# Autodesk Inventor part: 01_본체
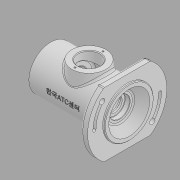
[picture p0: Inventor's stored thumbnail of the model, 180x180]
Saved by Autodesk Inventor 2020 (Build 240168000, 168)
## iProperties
Created: 2022-05
Part Number: 01_본체
Material: 일반
Document SubType Name: Modeling
Designer: User
Density: 1 g/cm^3
Appearance: 기본값
Author: User
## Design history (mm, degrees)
sketch "스케치1"
  geometry: L1 (0, 0)-(115, 0); L2 (0, 0)-(0, 32); L3 (0, 32)-(102, 32); L4 (102, 32)-(102, 58); L5 (102, 58)-(112, 58); L6 (112, 58)-(112, 36); L7 (112, 36)-(115, 36); L8 (115, 36)-(115, 0); L9 (0, 22.5)-(8, 22.5); L10 (8, 22.5)-(8, 24); L11 (8, 24)-(11, 24); L12 (11, 24)-(11, 22.5); L13 (11, 22.5)-(22, 22.5); L14 (22, 22.5)-(22, 17.5); L15 (22, 17.5)-(24.25, 17.5); L16 (24.25, 17.5)-(24.25, 18.5); L17 (24.25, 18.5)-(26, 18.5); L18 (26, 18.5)-(26, 17.5); L19 (26, 17.5)-(37, 17.5); L20 (37, 17.5)-(37, 27); L21 (37, 27)-(75, 27); L22 (75, 27)-(75, 17.5); L23 (75, 17.5)-(86, 17.5); L24 (86, 17.5)-(86, 15); L25 (86, 15)-(91, 15); L26 (91, 15)-(91, 11); L27 (91, 11)-(93.7, 11); L28 (93.7, 11)-(93.7, 15); L29 (101, 20)-(115, 30); L30 (100.3, 15)-(93.7, 15); L31 (101, 20)-(101, 15.404); L32 (101, 15.404)-(100.3, 15)
  constraints: 65 end point, 23 perpendicular, 8 point on line, 2 vertical, 1 horizontal, 1 parallel
  dimensions: "d0" = 115 distance of L1.start L1.end; "d1" = 102 distance of L2.end L3.end; "d2" = 3 distance of L6.end L7.end; "d3" = 72 diameter of L7 L1; "d4" = 64 diameter of L3 L1; "d5" = 116 diameter of L5 L1; "d6" = 14 distance from line of L8 L29.start; "d7" = 60 diameter of L29.end L1; "d8" = 40 diameter of L29.start L1; "d9" = 30 diameter of L30 L1; "d10" = 30 deg angle of L30 L32; "d11" = 0.7 horizontal distance of L30.start L31.end; "d12" = 7.3 distance between parallel lines of L28 L31; "d13" = 22 diameter of L27 L1; "d14" = 5 distance of L24.end L25.end; "d15" = 11 distance of L22.end L23.end; "d16" = 38 distance of L20.end L21.end; "d17" = 11 distance of L18.end L19.end; "d18" = 30 diameter of L25 L1; "d19" = 35 diameter of L23 L1; "d20" = 54 diameter of L21 L1; "d21" = 37 diameter of L17 L1; "d22" = 4 distance from line of L14.end L18; "d23" = 1.75 distance of L16.end L17.end; "d24" = 8 distance of L9.start L9.end; "d25" = 3 distance of L10.end L11.end; "d26" = 22 distance between parallel lines of L14 L2; "d27" = 45 diameter of L9 L1; "d28" = 48 diameter of L11 L1
revolve "회전1" sketch "스케치1" stored, may be unused: angle "d29" = 90 deg
sketch "스케치2"
  geometry: L1 (-33.985, 47)-(33.985, 47); L2 (-58, 0)-(58, 0); L3 (-33.985, -47)-(33.985, -47); A1 r 58 centre (0, 0) between (-33.985, 47) and (33.985, 47) reference; 2 further points
  constraints: 6 end point, 6 point on circle, 2 horizontal, 1 coincident, 1 midpoint, 1 parallel, 1 other
  dimensions: "d30" = 94 distance between parallel lines of L3 L1
extrude "돌출1" cut sketch "스케치2" extent not by distance; stored distance "d31" = 0; taper "d32" = 0 deg
sketch "스케치3"
  geometry: L1 (33.985, -47)-(-33.985, -47) reference; L2 (-33.985, 47)-(33.985, 47) reference; L3 (0, 0)-(48, 0); L4 (0, 0)-(36.77, 30.854); L5 (0, 0)-(-48, 0); L6 (0, 0)-(-36.77, -30.854); C1 r 36 at (0, 0) reference; A1 r 58 centre (0, 0) between (-33.985, 47) and (-33.985, -47) reference; A2 r 58 centre (0, 0) between (33.985, -47) and (33.985, 47) reference; A3 r 48 centre (0, 0) between (48, 0) and (36.77, 30.854); 2 further points
  constraints: 8 end point, 4 point on circle, 3 coincident, 2 horizontal, 1 centre point
  dimensions: "d33" = 48 radius of A3; "d34" = 40 deg angle of L3 L4; "d35" = 40 deg angle of L6 L5
hole "구멍1" sketch "스케치3" at (36.77, 30.854), (-36.77, -30.854) diameter "d36" = 8; stored, may be unused: countersink angle "d40" = 90 deg, drill point angle "d42" = 118 deg; dims "d37" = 12, "d38" = 4, "d39" = 2, "d41" = 8
sketch "스케치4"
  geometry: L1 (33.985, -47)-(-33.985, -47) reference; L2 (-33.985, 47)-(33.985, 47) reference; L3 (-48, 0)-(48, 0); C1 r 4 at (36.77, 30.854) reference; C2 r 4 at (-36.77, -30.854) reference; C3 r 36 at (0, 0) reference; A1 r 58 centre (0, 0) between (-33.985, 47) and (-33.985, -47) reference; A2 r 58 centre (0, 0) between (33.985, -47) and (33.985, 47) reference; A3 r 48 centre (0, 0) between (36.77, 30.854) and (-48, 0); A4 r 48 centre (0, 0) between (48, 0) and (36.77, 30.854); A5 r 52 centre (0, 0) between (52, 0) and (39.834, 33.425); A6 r 44 centre (0, 0) between (44, 0) and (33.706, 28.283); A7 r 4 centre (48, 0) between (44, 0) and (52, 0); A8 r 4 centre (36.77, 30.854) between (39.834, 33.425) and (33.706, 28.283); A9 r 48 centre (0, 0) between (-48, 0) and (-36.77, -30.854); A10 r 52 centre (0, 0) between (-52, 0) and (-39.834, -33.425); A11 r 44 centre (0, 0) between (-44, 0) and (-33.706, -28.283); A12 r 4 centre (-48, 0) between (-44, 0) and (-52, 0); A13 r 4 centre (-36.77, -30.854) between (-39.834, -33.425) and (-33.706, -28.283); 6 further points
  constraints: 23 point on circle, 11 centre point, 8 tangent, 4 coincident, 2 concentric, 2 end point, 1 horizontal, 1 midpoint
extrude "돌출2" cut sketch "스케치4" distance "d43" = 4.4; taper "d44" = 0 deg
sketch "스케치5"
  geometry: A1 r 4 centre (48, 0) between (44, 0) and (52, 0) reference; A2 r 52 centre (0, 0) between (52, 0) and (39.834, 33.425) reference; A3 r 4 centre (36.77, 30.854) between (33.706, 28.283) and (39.834, 33.425) reference; A4 r 44 centre (0, 0) between (44, 0) and (33.706, 28.283) reference; A5 r 4 centre (-48, 0) between (-44, 0) and (-52, 0) reference; A6 r 52 centre (0, 0) between (-52, 0) and (-39.834, -33.425) reference; A7 r 4 centre (-36.77, -30.854) between (-33.706, -28.283) and (-39.834, -33.425) reference; A8 r 44 centre (0, 0) between (-44, 0) and (-33.706, -28.283) reference; A9 r 50.25 centre (0, 0) between (50.25, 0) and (36.233, 34.818); A10 r 2.25 centre (48, 0) between (45.75, 0) and (50.25, 0); A11 r 45.75 centre (0, 0) between (45.75, 0) and (32.885, 31.806); A12 r 50.25 centre (0, 0) between (-50.25, 0) and (-40.58, -29.636); A13 r 2.25 centre (-48, 0) between (-45.75, 0) and (-50.25, 0); A14 r 45.75 centre (0, 0) between (-45.75, 0) and (-37.033, -26.862); 3 further points
  constraints: 16 point on circle, 6 centre point, 4 other
  dimensions: "d45" = 2.25 radius of A10; "d46" = 2.25 radius of A13
extrude "돌출3" cut sketch "스케치5" extent not by distance; stored distance "d47" = 0; taper "d48" = 0 deg
node "작업 평면1"
sketch "스케치6"
  geometry: C1 r 25 at (-56, 0); 1 further point
  constraints: 1 centre point, 1 horizontal alignment
  dimensions: "d50" = 25 radius of C1; "d51" = 56 distance of C1.centre point (0, 0)
extrude "돌출4" join sketch "스케치6" stored distance "d52" = 4.4; taper "d53" = 5 deg
sketch "스케치7"
  geometry: L1 (0, 0)-(0, 20.5); C1 r 25 at (0, 0) reference; 2 further points
  constraints: 2 end point, 1 coincident, 1 vertical
  dimensions: "d54" = 20.5 distance of L1.start L1.end
hole "구멍2" sketch "스케치7" at (0, 20.5) diameter "d55" = 2.62111; stored, may be unused: countersink angle "d59" = 90 deg, drill point angle "d61" = 118 deg; dims "d56" = 6, "d57" = 4, "d58" = 2, "d60" = 8
sketch "스케치8"
  geometry: C1 r 25 at (0, 0) reference; 2 further points
  constraints: 1 coincident
hole "구멍3" sketch "스케치8" at (0, 0) diameter "d65" = 32; stored, may be unused: countersink angle "d69" = 90 deg, drill point angle "d71" = 118 deg; dims "d66" = 6, "d67" = 4, "d68" = 2, "d70" = 8
fillet "모깎기1" dims "d72" = 0.5, "d73" = 0.6
fillet "모깎기2" dims "d74" = 3
chamfer "모따기1" distance "d75" = 1; stored, may be unused: second distance "d76" = 2, angle "d77" = 45 deg
fillet "모깎기3" dims "d78" = 3
node "작업 평면2"
sketch "스케치9"
  geometry: L1 (61, -46.4)-(61, 46.4) reference; 2 further points
  constraints: 1 horizontal alignment, 1 other
  dimensions: "d79" = 62 distance from line of point (-1, 0) L1
feature "엠보싱1" sketch "스케치9" dims "d0" = 115, "d1" = 102, "d2" = 3, "d3" = 72, "d4" = 64, "d5" = 116, "d6" = 14, "d7" = 60, "d8" = 40, "d9" = 30, "d10" = 30 deg, "d11" = 0.7, "d12" = 7.3, "d13" = 22, "d14" = 5, "d15" = 11, "d16" = 38, "d17" = 11, "d18" = 30, "d19" = 35, "d20" = 54, "d21" = 37, "d22" = 4, "d23" = 1.75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
feature "스레드1" dims "d82" = 8, "d83" = 0
node "솔리드1"
pattern_circular "원형 패턴1" dims angle "d63" = 360 deg
node "투영된 루프1"
node "투영된 루프2"
node "투영된 루프3"
node "투영된 루프4"
node "투영된 루프5"
feature "A9D066F2-1C7D-4E18-AEED-F7BC21143FA4" dims "d82" = 8, "d83" = 0
other parameters: "d49" = 38
